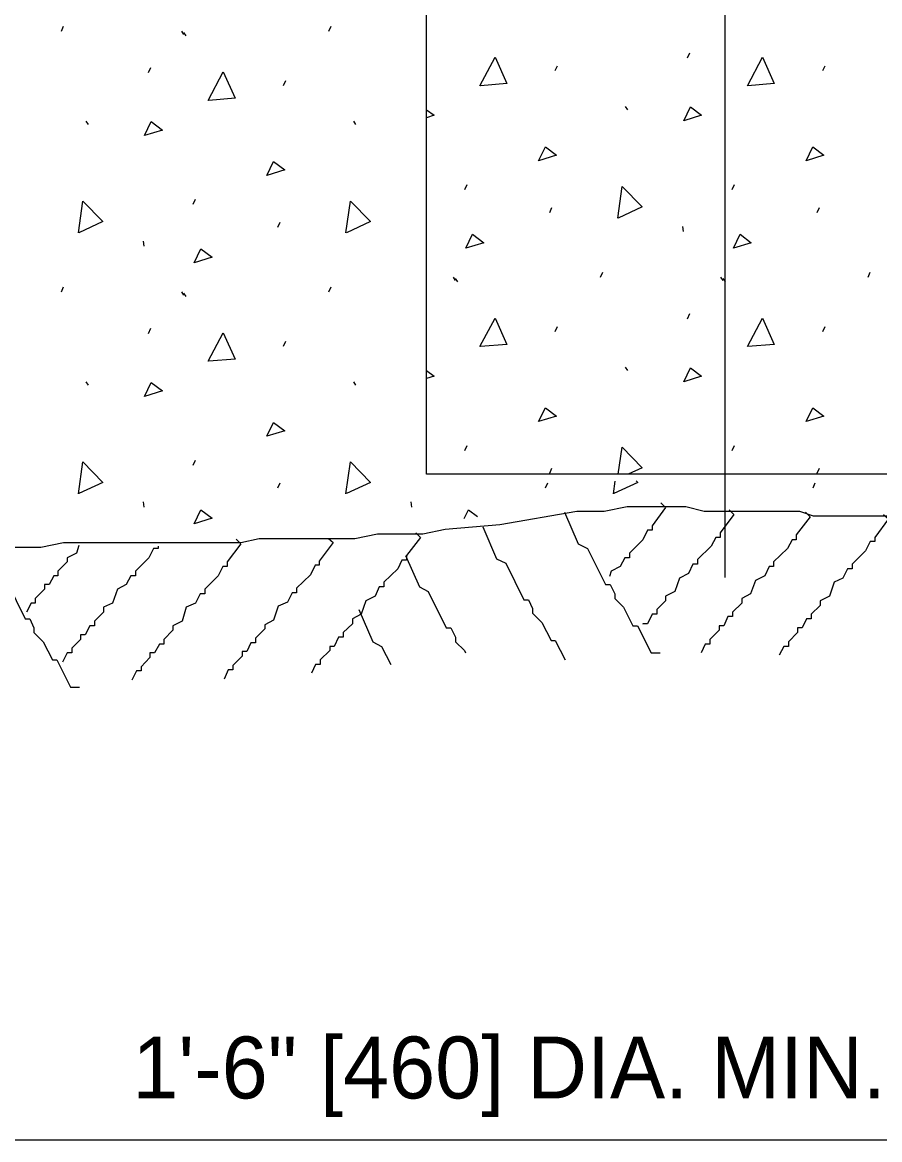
# Model space of a CAD drawing. Extents: x 49991.4 to 50021, y 49987.6 to 50011.4.
# Drawn here: x 50002.62 to 50003.451, y 49990.078 to 49991.161 of the extents above; entities that cross this region are included whole.
import ezdxf

# ---------------------------------------------------------------- set-up
doc = ezdxf.new("R2010")
doc.units = 0
for name, color, linetype in [('Level 1', 7, 'Continuous'), ('Level 2', 7, 'Continuous'), ('Level 3', 7, 'Continuous'), ('Level 5', 7, 'Continuous')]:
    doc.layers.add(name, color=color, linetype=linetype)

msp = doc.modelspace()

# ---------------------------------------------------------------- linework, layer by layer
at = {"layer": 'Level 1'}
for p, q in [((50003.0123, 49990.7229), (50003.0123, 49996.1466)), ((50002.6582, 49991.1525), (50002.6604, 49991.1574)), ((50002.7746, 49991.1525), (50002.7767, 49991.1493)), ((50002.7767, 49991.1513), (50002.7789, 49991.148)), ((50002.9175, 49991.1525), (50002.9197, 49991.1574)), ((50003.2653, 49991.1266), (50003.2675, 49991.1315)), ((50002.7426, 49991.1124), (50002.7448, 49991.1173)), ((50003.137, 49991.1142), (50003.1392, 49991.119)), ((50003.3963, 49991.1142), (50003.3985, 49991.119)), ((50002.8736, 49991.0999), (50002.8758, 49991.1048)), ((50003.2047, 49991.0795), (50003.2069, 49991.0763)), ((50002.682, 49991.0653), (50002.6842, 49991.0621)), ((50002.9413, 49991.0653), (50002.9435, 49991.0621)), ((50003.0493, 49990.9989), (50003.0515, 49991.0037)), ((50003.3086, 49990.9989), (50003.3108, 49991.0037)), ((50002.786, 49990.9846), (50002.7881, 49990.9895)), ((50003.1316, 49990.9767), (50003.1338, 49990.9815)), ((50003.3909, 49990.9767), (50003.3931, 49990.9815)), ((50002.8682, 49990.9624), (50002.8704, 49990.9673)), ((50003.2603, 49990.9631), (50003.2609, 49990.9582)), ((50002.7376, 49990.9489), (50002.7382, 49990.944)), ((50003.0379, 49990.9139), (50003.0401, 49990.9106)), ((50003.0401, 49990.9126), (50003.0423, 49990.9094)), ((50003.1809, 49990.9139), (50003.183, 49990.9187)), ((50003.2973, 49990.9139), (50003.2994, 49990.9106)), ((50003.2994, 49990.9126), (50003.3016, 49990.9094)), ((50003.4402, 49990.9139), (50003.4423, 49990.9187)), ((50002.6582, 49990.8997), (50002.6604, 49990.9045)), ((50002.9175, 49990.8997), (50002.9197, 49990.9045)), ((50002.7746, 49990.8997), (50002.7767, 49990.8964)), ((50002.7767, 49990.8984), (50002.7789, 49990.8952)), ((50003.2653, 49990.8737), (50003.2675, 49990.8786)), ((50002.7426, 49990.8595), (50002.7448, 49990.8644)), ((50003.137, 49990.8613), (50003.1392, 49990.8662)), ((50003.3963, 49990.8613), (50003.3985, 49990.8662)), ((50002.8736, 49990.8471), (50002.8758, 49990.852)), ((50003.2047, 49990.8266), (50003.2069, 49990.8234)), ((50002.682, 49990.8124), (50002.6842, 49990.8092)), ((50002.9413, 49990.8124), (50002.9435, 49990.8092)), ((50003.0493, 49990.746), (50003.0515, 49990.7509)), ((50003.3086, 49990.746), (50003.3108, 49990.7509)), ((50002.786, 49990.7318), (50002.7881, 49990.7366)), ((50003.1316, 49990.7238), (50003.1338, 49990.7287)), ((50003.3909, 49990.7238), (50003.3931, 49990.7287)), ((50003.5903, 49990.7229), (50003.0123, 49990.7229)), ((50002.8682, 49990.7096), (50002.8704, 49990.7145)), ((50003.1275, 49990.7096), (50003.1297, 49990.7145)), ((50003.3869, 49990.7096), (50003.389, 49990.7145)), ((50002.7376, 49990.696), (50002.7382, 49990.6911)), ((50002.9969, 49990.696), (50002.9975, 49990.6911))]:
    msp.add_line(p, q, dxfattribs=at)
for points in [[(50003.0639, 49991.0995), (50003.0786, 49991.1272), (50003.0899, 49991.1017), (50003.0645, 49991.0995)], [(50003.3233, 49991.0995), (50003.3379, 49991.1272), (50003.3492, 49991.1017), (50003.3238, 49991.0995)], [(50002.8006, 49991.0853), (50002.8152, 49991.1129), (50002.8266, 49991.0875), (50002.8011, 49991.0853)], [(50003.0123, 49991.0763), (50003.0195, 49991.0709), (50003.0123, 49991.0686)], [(50003.2615, 49991.0654), (50003.268, 49991.079), (50003.2788, 49991.0709), (50003.2615, 49991.0654)], [(50002.7388, 49991.0512), (50002.7453, 49991.0648), (50002.7562, 49991.0566), (50002.7388, 49991.0512)], [(50003.1209, 49991.0267), (50003.1274, 49991.0403), (50003.1382, 49991.0322), (50003.1209, 49991.0267)], [(50003.3802, 49991.0267), (50003.3867, 49991.0403), (50003.3975, 49991.0322), (50003.3802, 49991.0267)], [(50002.8575, 49991.0125), (50002.864, 49991.0261), (50002.8748, 49991.0179), (50002.8575, 49991.0125)], [(50003.1975, 49990.9711), (50003.2018, 49991.002), (50003.2211, 49990.982), (50003.198, 49990.9712)], [(50002.6748, 49990.9568), (50002.6791, 49990.9878), (50002.6985, 49990.9678), (50002.6753, 49990.957)], [(50002.9341, 49990.9568), (50002.9384, 49990.9878), (50002.9578, 49990.9678), (50002.9346, 49990.957)], [(50003.0504, 49990.942), (50003.0569, 49990.9556), (50003.0677, 49990.9474), (50003.0504, 49990.942)], [(50003.3097, 49990.942), (50003.3162, 49990.9556), (50003.327, 49990.9474), (50003.3097, 49990.942)], [(50002.787, 49990.9278), (50002.7935, 49990.9413), (50002.8044, 49990.9332), (50002.787, 49990.9278)], [(50003.0639, 49990.8467), (50003.0786, 49990.8743), (50003.0899, 49990.8488), (50003.0645, 49990.8467)], [(50003.3233, 49990.8467), (50003.3379, 49990.8743), (50003.3492, 49990.8488), (50003.3238, 49990.8467)], [(50002.8006, 49990.8325), (50002.8152, 49990.8601), (50002.8266, 49990.8346), (50002.8011, 49990.8325)], [(50003.2615, 49990.8126), (50003.268, 49990.8261), (50003.2788, 49990.818), (50003.2615, 49990.8126)], [(50003.0123, 49990.8234), (50003.0195, 49990.818), (50003.0123, 49990.8157)], [(50002.7388, 49990.7984), (50002.7453, 49990.8119), (50002.7562, 49990.8038), (50002.7388, 49990.7984)], [(50003.1209, 49990.7739), (50003.1274, 49990.7874), (50003.1382, 49990.7793), (50003.1209, 49990.7739)], [(50003.3802, 49990.7739), (50003.3867, 49990.7874), (50003.3975, 49990.7793), (50003.3802, 49990.7739)], [(50002.8575, 49990.7597), (50002.864, 49990.7732), (50002.8748, 49990.7651), (50002.8575, 49990.7597)], [(50003.1981, 49990.7229), (50003.2018, 49990.7491), (50003.2211, 49990.7291), (50003.2078, 49990.7229)], [(50002.6748, 49990.704), (50002.6791, 49990.7349), (50002.6985, 49990.7149), (50002.6753, 49990.7042)], [(50002.9341, 49990.704), (50002.9384, 49990.7349), (50002.9578, 49990.7149), (50002.9346, 49990.7042)], [(50003.2155, 49990.7165), (50003.2171, 49990.7149), (50003.1939, 49990.7042)], [(50003.1934, 49990.704), (50003.1951, 49990.7163)], [(50003.2394, 49990.6951), (50003.2439, 49990.6905), (50003.2309, 49990.673), (50003.2309, 49990.6685), (50003.2264, 49990.6685), (50003.2219, 49990.6594), (50003.2088, 49990.6464), (50003.2088, 49990.6419), (50003.2043, 49990.6419), (50003.1998, 49990.6334), (50003.1913, 49990.6289), (50003.1896, 49990.6238)], [(50002.5898, 49990.6521), (50002.6384, 49990.6521), (50002.6604, 49990.6566), (50002.7616, 49990.6566), (50002.8323, 49990.6566), (50002.8498, 49990.6606), (50002.9426, 49990.6606), (50002.9646, 49990.6651), (50003.0087, 49990.6651), (50003.0302, 49990.6696), (50003.0833, 49990.6741), (50003.158, 49990.6872), (50003.1845, 49990.6872), (50003.2066, 49990.6917), (50003.2637, 49990.6917), (50003.2812, 49990.6872), (50003.3739, 49990.6872), (50003.3869, 49990.6826), (50003.4667, 49990.6826)], [(50002.787, 49990.6749), (50002.7935, 49990.6885), (50002.8044, 49990.6803), (50002.787, 49990.6749)], [(50003.0488, 49990.68), (50003.0528, 49990.6885), (50003.0615, 49990.682)], [(50003.1461, 49990.686), (50003.1591, 49990.6555), (50003.1681, 49990.651), (50003.1857, 49990.6159), (50003.1902, 49990.6159), (50003.1947, 49990.6069), (50003.1947, 49990.6023), (50003.2032, 49990.5939), (50003.2122, 49990.5758), (50003.2168, 49990.5758), (50003.2298, 49990.5498), (50003.2388, 49990.5498)], [(50003.3055, 49990.6883), (50003.31, 49990.6838), (50003.297, 49990.6662), (50003.297, 49990.6617), (50003.2925, 49990.6617), (50003.288, 49990.6532), (50003.275, 49990.6402), (50003.275, 49990.6357), (50003.2705, 49990.6357), (50003.266, 49990.6267), (50003.2575, 49990.6221), (50003.2529, 49990.6091), (50003.2439, 49990.6046), (50003.2439, 49990.6001), (50003.2354, 49990.5916), (50003.2354, 49990.5871), (50003.2309, 49990.5871), (50003.2264, 49990.578), (50003.2219, 49990.578), (50003.2219, 49990.5775)], [(50003.3796, 49990.686), (50003.3841, 49990.6815), (50003.3705, 49990.664), (50003.3705, 49990.6594), (50003.3666, 49990.6594), (50003.3621, 49990.651), (50003.3485, 49990.638), (50003.3485, 49990.6334), (50003.3445, 49990.6334), (50003.34, 49990.6244), (50003.331, 49990.6199), (50003.3264, 49990.6069), (50003.318, 49990.6023), (50003.318, 49990.5978), (50003.3089, 49990.5893), (50003.3089, 49990.5848), (50003.3044, 49990.5848), (50003.3004, 49990.5758), (50003.2959, 49990.5758), (50003.2959, 49990.5718), (50003.2869, 49990.5628), (50003.2869, 49990.5582), (50003.2823, 49990.5582), (50003.2784, 49990.5498)], [(50003.4553, 49990.6838), (50003.4599, 49990.6798), (50003.4469, 49990.6617), (50003.4469, 49990.6578), (50003.4423, 49990.6578), (50003.4378, 49990.6487), (50003.4248, 49990.6357), (50003.4248, 49990.6312), (50003.4203, 49990.6312), (50003.4158, 49990.6221), (50003.4073, 49990.6182), (50003.4028, 49990.6046), (50003.3937, 49990.6001), (50003.3937, 49990.5956), (50003.3852, 49990.5871), (50003.3852, 49990.5826), (50003.3807, 49990.5826), (50003.3762, 49990.5741), (50003.3717, 49990.5741), (50003.3717, 49990.5696), (50003.3632, 49990.5605), (50003.3632, 49990.556), (50003.3587, 49990.556), (50003.3541, 49990.5475)], [(50003.0019, 49990.6662), (50003.0065, 49990.6617), (50002.9929, 49990.6442), (50002.9929, 49990.6397), (50002.9884, 49990.6397), (50002.9844, 49990.6312), (50002.9708, 49990.6182), (50002.9708, 49990.6137), (50002.9663, 49990.6137), (50002.9624, 49990.6046), (50002.9533, 49990.6001), (50002.9488, 49990.5871), (50002.9403, 49990.5826), (50002.9403, 49990.578), (50002.9313, 49990.5696), (50002.9313, 49990.565), (50002.9267, 49990.565), (50002.9228, 49990.556), (50002.9183, 49990.556), (50002.9183, 49990.552), (50002.9092, 49990.543), (50002.9092, 49990.5385), (50002.9047, 49990.5385), (50002.9007, 49990.53)], [(50003.0669, 49990.6719), (50003.0799, 49990.6408), (50003.089, 49990.6368), (50003.1065, 49990.6012), (50003.111, 49990.6012), (50003.115, 49990.5927), (50003.115, 49990.5882), (50003.124, 49990.5792), (50003.1331, 49990.5616), (50003.137, 49990.5616), (50003.1467, 49990.543)], [(50002.5836, 49990.6532), (50002.5966, 49990.6221), (50002.6056, 49990.6182), (50002.6231, 49990.5826), (50002.6277, 49990.5826), (50002.6316, 49990.5741), (50002.6316, 49990.5696), (50002.6407, 49990.5605), (50002.6497, 49990.543), (50002.6537, 49990.543), (50002.6672, 49990.5164), (50002.6757, 49990.5164)], [(50002.6751, 49990.6538), (50002.6729, 49990.6464), (50002.6638, 49990.6419), (50002.6638, 49990.638), (50002.6548, 49990.6289), (50002.6548, 49990.6244), (50002.6508, 49990.6244), (50002.6463, 49990.6159), (50002.6418, 49990.6159), (50002.6418, 49990.6114), (50002.6327, 49990.6023), (50002.6327, 49990.5978), (50002.6288, 49990.5978), (50002.6243, 49990.5893)], [(50002.752, 49990.6532), (50002.752, 49990.651), (50002.7475, 49990.651), (50002.743, 49990.6419), (50002.73, 49990.6289), (50002.73, 49990.6244), (50002.7255, 49990.6244), (50002.7209, 49990.6159), (50002.7125, 49990.6114), (50002.7079, 49990.5978), (50002.6989, 49990.5939), (50002.6989, 49990.5893), (50002.6904, 49990.5803), (50002.6904, 49990.5758), (50002.6859, 49990.5758), (50002.6814, 49990.5673), (50002.6768, 49990.5673), (50002.6768, 49990.5628), (50002.6684, 49990.5543), (50002.6684, 49990.5498), (50002.6638, 49990.5498), (50002.6593, 49990.5407)], [(50002.8278, 49990.66), (50002.8323, 49990.6555), (50002.8188, 49990.638), (50002.8188, 49990.6334), (50002.8148, 49990.6334), (50002.8103, 49990.6244), (50002.7973, 49990.6114), (50002.7973, 49990.6069), (50002.7927, 49990.6069), (50002.7882, 49990.5978), (50002.7792, 49990.5939), (50002.7752, 49990.5803), (50002.7662, 49990.5758), (50002.7662, 49990.5718), (50002.7577, 49990.5628), (50002.7577, 49990.5582), (50002.7532, 49990.5582), (50002.7486, 49990.5498), (50002.7441, 49990.5498), (50002.7441, 49990.5452), (50002.7356, 49990.5362), (50002.7356, 49990.5322), (50002.7311, 49990.5322), (50002.7266, 49990.5232)], [(50002.9171, 49990.6606), (50002.9216, 49990.6566), (50002.9081, 49990.6385), (50002.9081, 49990.6346), (50002.9041, 49990.6346), (50002.8996, 49990.6255), (50002.886, 49990.6125), (50002.886, 49990.608), (50002.8821, 49990.608), (50002.8775, 49990.599), (50002.8685, 49990.595), (50002.864, 49990.5814), (50002.8555, 49990.5769), (50002.8555, 49990.5729), (50002.8465, 49990.5639), (50002.8465, 49990.5594), (50002.8419, 49990.5594), (50002.838, 49990.5509), (50002.8334, 49990.5509), (50002.8334, 49990.5464), (50002.8244, 49990.5373), (50002.8244, 49990.5334), (50002.8199, 49990.5334), (50002.8159, 49990.5243)], [(50002.9918, 49990.6442), (50003.0053, 49990.6137), (50003.0138, 49990.6091), (50003.0313, 49990.5741), (50003.0358, 49990.5741), (50003.0404, 49990.565), (50003.0404, 49990.5605), (50003.0489, 49990.552), (50003.05, 49990.5498)], [(50002.9465, 49990.5916), (50002.9601, 49990.5605), (50002.9686, 49990.556), (50002.9776, 49990.5385)]]:
    msp.add_lwpolyline(points, dxfattribs=at)
at = {"layer": 'Level 3'}
msp.add_line((50002.0103, 49990.0777), (50004.5939, 49990.0777), dxfattribs=at)
at = {"layer": 'Level 5'}
msp.add_line((50003.3013, 49996.8665), (50003.3013, 49990.6229), dxfattribs=at)

# ---------------------------------------------------------------- texts
at = {"layer": 'Level 2'}
msp.add_text('1\'-6" [460] DIA. MIN.', height=0.06, dxfattribs=at).set_placement((50002.727, 49990.1177))

doc.saveas('drawing.dxf')
